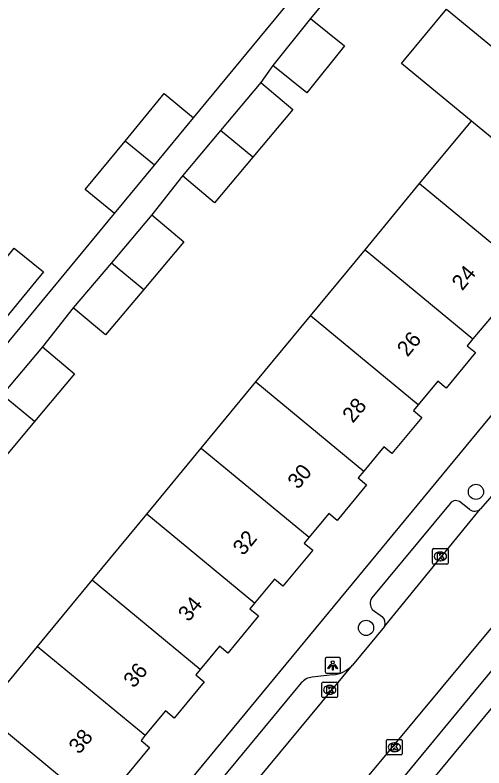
# Model space of a CAD drawing. Extents: x 162074 to 163034, y 381824 to 382557.
# Drawn here: x 162299.86 to 162330.07, y 382106.65 to 382155.17 of the extents above; entities that cross this region are included whole.
import ezdxf

# ---------------------------------------------------------------- set-up
doc = ezdxf.new("R2010")
doc.units = 0
for name, color, linetype in [('IMGEO_Boom', 7, 'Continuous'), ('IMGEO_Kolk', 7, 'Continuous'), ('IMGEO_Lichtpunt', 7, 'Continuous'), ('IMGEO_Pand', 7, 'Continuous'), ('IMGEO_Pand_nummerreeks', 7, 'Continuous'), ('IMGEO_Rijbaan_lokaal_open', 7, 'Continuous'), ('IMGEO_Voetpad_open', 7, 'Continuous')]:
    doc.layers.add(name, color=color, linetype=linetype)

msp = doc.modelspace()

# ---------------------------------------------------------------- linework, layer by layer
at = {"layer": 'IMGEO_Boom'}
for centre in [(162329.556, 382124.437), (162322.476, 382115.671)]:
    msp.add_circle(centre, 0.489, dxfattribs=at)
at = {"layer": 'IMGEO_Kolk'}
for p, q in [((162326.838, 382120.779), (162327.69, 382120.779)), ((162326.763, 382119.853), (162326.763, 382120.705)), ((162327.251, 382120.559), (162327.276, 382120.559)), ((162327.764, 382120.705), (162327.764, 382119.853)), ((162327.69, 382119.779), (162326.838, 382119.779)), ((162327.274, 382119.999), (162327.249, 382119.999)), ((162319.633, 382111.254), (162319.633, 382112.106)), ((162319.708, 382112.18), (162320.56, 382112.18)), ((162320.634, 382112.106), (162320.634, 382111.254)), ((162320.121, 382111.96), (162320.146, 382111.96)), ((162320.56, 382111.18), (162319.708, 382111.18)), ((162320.144, 382111.4), (162320.119, 382111.4)), ((162323.801, 382107.555), (162323.801, 382108.407)), ((162323.876, 382108.481), (162324.728, 382108.481)), ((162324.289, 382108.261), (162324.314, 382108.261)), ((162324.802, 382108.407), (162324.802, 382107.555)), ((162324.312, 382107.701), (162324.287, 382107.701)), ((162324.728, 382107.481), (162323.876, 382107.481))]:
    msp.add_line(p, q, dxfattribs=at)
for points in [[(162326.838, 382120.779), (162327.69, 382120.779)], [(162326.763, 382119.853), (162326.763, 382120.705)], [(162327.084, 382120.479), (162327.207, 382120.479), (162327.207, 382120.328), (162327.337, 382120.479), (162327.501, 382120.479), (162327.355, 382120.328), (162327.508, 382120.079), (162327.356, 382120.079), (162327.271, 382120.243), (162327.207, 382120.176), (162327.207, 382120.079), (162327.084, 382120.079), (162327.084, 382120.479)], [(162327.764, 382120.705), (162327.764, 382119.853)], [(162327.69, 382119.779), (162326.838, 382119.779)], [(162319.633, 382111.254), (162319.633, 382112.106)], [(162319.708, 382112.18), (162320.56, 382112.18)], [(162320.634, 382112.106), (162320.634, 382111.254)], [(162319.954, 382111.88), (162320.077, 382111.88), (162320.077, 382111.729), (162320.207, 382111.88), (162320.371, 382111.88), (162320.225, 382111.729), (162320.378, 382111.48), (162320.226, 382111.48), (162320.141, 382111.644), (162320.077, 382111.577), (162320.077, 382111.48), (162319.954, 382111.48), (162319.954, 382111.88)], [(162320.56, 382111.18), (162319.708, 382111.18)], [(162323.801, 382107.555), (162323.801, 382108.407)], [(162323.876, 382108.481), (162324.728, 382108.481)], [(162324.122, 382108.181), (162324.245, 382108.181), (162324.245, 382108.03), (162324.375, 382108.181), (162324.539, 382108.181), (162324.393, 382108.03), (162324.546, 382107.781), (162324.394, 382107.781), (162324.309, 382107.945), (162324.245, 382107.878), (162324.245, 382107.781), (162324.122, 382107.781), (162324.122, 382108.181)], [(162324.802, 382108.407), (162324.802, 382107.555)], [(162324.728, 382107.481), (162323.876, 382107.481)]]:
    msp.add_lwpolyline(points, dxfattribs=at)
for centre, start, end in [((162326.84, 382120.703), 91.552, 178.448), ((162326.84, 382120.703), 91.552, 178.448), ((162327.688, 382120.703), 1.552, 88.448), ((162327.688, 382120.703), 1.552, 88.448), ((162326.84, 382119.855), 181.552, 268.448), ((162326.84, 382119.855), 181.552, 268.448), ((162327.688, 382119.855), 271.552, 358.448), ((162327.688, 382119.855), 271.552, 358.448), ((162319.71, 382112.104), 91.552, 178.448), ((162319.71, 382112.104), 91.552, 178.448), ((162320.558, 382112.104), 1.552, 88.448), ((162320.558, 382112.104), 1.552, 88.448), ((162319.71, 382111.256), 181.552, 268.448), ((162319.71, 382111.256), 181.552, 268.448), ((162320.558, 382111.256), 271.552, 358.448), ((162320.558, 382111.256), 271.552, 358.448), ((162323.878, 382108.405), 91.552, 178.448), ((162323.878, 382108.405), 91.552, 178.448), ((162324.726, 382108.405), 1.552, 88.448), ((162324.726, 382108.405), 1.552, 88.448), ((162323.878, 382107.557), 181.552, 268.448), ((162323.878, 382107.557), 181.552, 268.448), ((162324.726, 382107.557), 271.552, 358.448), ((162324.726, 382107.557), 271.552, 358.448)]:
    msp.add_arc(centre, 0.0765, start, end, dxfattribs=at)
for centre, major_axis, ratio, start_param, end_param in [((162327.25, 382120.279), (-0.387, 0.002), 0.722429, 4.712389, 7.853982), ((162327.275, 382120.279), (-0.39, 0.002), 0.717154, 1.570796, 4.712389), ((162320.12, 382111.68), (-0.387, 0.002), 0.722429, 4.712389, 7.853982), ((162320.145, 382111.68), (-0.39, 0.002), 0.717154, 1.570796, 4.712389), ((162324.288, 382107.981), (-0.387, 0.002), 0.722429, 4.712389, 7.853982), ((162324.313, 382107.981), (-0.39, 0.002), 0.717154, 1.570796, 4.712389)]:
    msp.add_ellipse(centre, major_axis=major_axis, ratio=ratio, start_param=start_param, end_param=end_param, dxfattribs=at)
at = {"layer": 'IMGEO_Lichtpunt'}
for p, q in [((162319.832, 382113.66), (162319.832, 382112.853)), ((162319.832, 382113.66), (162319.832, 382112.853)), ((162320.734, 382113.755), (162319.926, 382113.755)), ((162320.734, 382113.755), (162319.926, 382113.755)), ((162320.828, 382112.853), (162320.828, 382113.66)), ((162320.828, 382112.853), (162320.828, 382113.66)), ((162319.926, 382112.759), (162320.734, 382112.759)), ((162319.926, 382112.759), (162320.734, 382112.759))]:
    msp.add_line(p, q, dxfattribs=at)
for points in [[(162320.206, 382113.324), (162320.245, 382113.296), (162320.057, 382113.034), (162320.019, 382113.061), (162320.206, 382113.324)], [(162320.308, 382113.276), (162320.355, 382113.276), (162320.355, 382112.954), (162320.308, 382112.954), (162320.308, 382113.276)], [(162320.418, 382113.296), (162320.456, 382113.323), (162320.643, 382113.061), (162320.604, 382113.033), (162320.418, 382113.296)]]:
    msp.add_lwpolyline(points, dxfattribs=at)
msp.add_circle((162320.331, 382113.458), 0.0994, dxfattribs=at)
for centre, start, end in [((162319.926, 382113.66), 90, 180), ((162319.926, 382113.66), 90, 180), ((162320.734, 382113.66), 0, 90), ((162320.734, 382113.66), 0, 90), ((162319.926, 382112.853), 180, 270), ((162319.926, 382112.853), 180, 270), ((162320.734, 382112.853), 270, 0), ((162320.734, 382112.853), 270, 360)]:
    msp.add_arc(centre, 0.0946, start, end, dxfattribs=at)
at = {"layer": 'IMGEO_Pand'}
for points in [[(162329.26, 382148.338), (162324.766, 382152.048), (162324.954, 382152.276), (162327.662, 382155.556), (162335.775, 382148.858), (162339.631, 382145.675), (162336.921, 382142.391), (162336.734, 382142.165)], [(162318.898, 382154.941), (162321.086, 382153.179), (162318.653, 382150.158), (162316.465, 382151.92)], [(162318.898, 382154.941), (162316.465, 382151.92)], [(162315.7, 382150.823), (162313.101, 382147.733)], [(162315.7, 382150.823), (162317.769, 382149.084), (162315.185, 382146.011)], [(162306.947, 382147.046), (162309.46, 382150.106), (162311.357, 382148.541)], [(162308.841, 382145.49), (162311.357, 382148.541)], [(162325.929, 382144.303), (162329.26, 382148.338)], [(162336.734, 382142.165), (162329.26, 382148.338)], [(162313.101, 382147.733), (162310.648, 382144.814)], [(162315.185, 382146.011), (162313.101, 382147.733)], [(162306.275, 382142.38), (162304.387, 382143.929), (162306.947, 382147.046)], [(162308.841, 382145.49), (162306.947, 382147.046)], [(162315.185, 382146.011), (162312.717, 382143.075), (162310.648, 382144.814)], [(162306.275, 382142.38), (162308.841, 382145.49)], [(162322.412, 382140.042), (162325.929, 382144.303)], [(162325.929, 382144.303), (162332.914, 382138.534)], [(162308.665, 382142.301), (162306.065, 382139.209)], [(162308.665, 382142.301), (162310.734, 382140.562), (162308.15, 382137.488)], [(162297.368, 382137.17), (162299.807, 382140.146), (162301.697, 382138.61), (162299.257, 382135.631)], [(162318.895, 382135.782), (162322.412, 382140.042)], [(162322.412, 382140.042), (162329.366, 382134.298)], [(162306.065, 382139.209), (162303.613, 382136.292)], [(162306.065, 382139.209), (162308.15, 382137.488)], [(162332.914, 382138.534), (162332.499, 382138.032), (162332.977, 382137.637), (162331.039, 382135.289), (162330.531, 382135.709), (162329.366, 382134.298)], [(162308.15, 382137.488), (162305.682, 382134.553), (162303.613, 382136.292)], [(162315.377, 382131.52), (162318.895, 382135.782)], [(162325.839, 382130.046), (162318.895, 382135.782)], [(162329.366, 382134.298), (162328.996, 382133.85), (162329.525, 382133.413), (162327.631, 382131.119), (162327.092, 382131.564), (162325.839, 382130.046)], [(162301.631, 382133.78), (162299.032, 382130.689)], [(162301.631, 382133.78), (162303.7, 382132.041), (162301.116, 382128.968)], [(162311.86, 382127.26), (162315.377, 382131.52)], [(162315.377, 382131.52), (162322.333, 382125.776)], [(162301.116, 382128.968), (162299.032, 382130.689)], [(162325.839, 382130.046), (162325.538, 382129.681), (162326.071, 382129.241), (162324.147, 382126.91), (162323.625, 382127.341), (162322.333, 382125.776)], [(162301.116, 382128.968), (162298.648, 382126.032), (162296.579, 382127.771)], [(162308.343, 382122.999), (162311.86, 382127.26)], [(162311.86, 382127.26), (162318.81, 382121.519)], [(162322.333, 382125.776), (162321.977, 382125.345), (162322.515, 382124.901), (162320.616, 382122.599), (162320.072, 382123.048), (162318.81, 382121.519)], [(162304.825, 382118.739), (162308.343, 382122.999)], [(162315.29, 382117.261), (162308.343, 382122.999)], [(162318.81, 382121.519), (162318.494, 382121.136), (162319.038, 382120.686), (162317.117, 382118.359), (162316.57, 382118.811), (162315.29, 382117.261)], [(162301.308, 382114.477), (162304.825, 382118.739)], [(162311.794, 382112.982), (162304.825, 382118.739)], [(162315.29, 382117.261), (162314.992, 382116.9), (162315.544, 382116.444), (162313.571, 382114.053), (162313.04, 382114.491), (162311.794, 382112.982)], [(162297.791, 382110.217), (162301.308, 382114.477)], [(162301.308, 382114.477), (162308.244, 382108.748)], [(162311.794, 382112.982), (162311.509, 382112.637), (162312.037, 382112.201), (162310.107, 382109.864), (162309.547, 382110.326), (162308.244, 382108.748)], [(162297.791, 382110.217), (162304.754, 382104.466)], [(162308.244, 382108.748), (162307.977, 382108.424), (162308.528, 382107.969), (162306.577, 382105.606), (162306.053, 382106.039), (162304.754, 382104.466)]]:
    msp.add_lwpolyline(points, dxfattribs=at)
at = {"layer": 'IMGEO_Rijbaan_lokaal_open'}
for points in [[(162331, 382124.675), (162329.86, 382123.349)], [(162323.66, 382115.771), (162329.86, 382123.349)], [(162336.118, 382122.382), (162316.921, 382099.281)], [(162323.66, 382115.771), (162321.603, 382113.278)], [(162310.148, 382099.454), (162321.603, 382113.278)]]:
    msp.add_lwpolyline(points, dxfattribs=at)
at = {"layer": 'IMGEO_Voetpad_open'}
for points in [[(162311.357, 382148.541), (162323.43, 382163.172), (162320.732, 382165.399)], [(162344.282, 382145.986), (162324.785, 382162.075), (162318.898, 382154.941)], [(162316.465, 382151.92), (162315.7, 382150.823)], [(162292.703, 382083.506), (162344.282, 382145.986)], [(162310.648, 382144.814), (162308.665, 382142.301)], [(162280.011, 382110.569), (162306.275, 382142.38)], [(162303.613, 382136.292), (162301.631, 382133.78)], [(162352.042, 382136.478), (162351.891, 382136.294), (162317.774, 382095.055)], [(162327.89, 382123.697), (162322.838, 382117.599)], [(162329.14, 382123.312), (162328.579, 382123.752)], [(162320.226, 382100.372), (162336.497, 382120.103)], [(162322.874, 382116.853), (162323.539, 382116.389)], [(162320.318, 382112.646), (162319.012, 382112.498)], [(162318.303, 382112.123), (162309.358, 382101.318)]]:
    msp.add_lwpolyline(points, dxfattribs=at)
for centre, radius, start, end in [((162328.26, 382123.399), 0.475, 47.934, 141.194), ((162329.478, 382123.762), 0.562, 233.0864, 312.7972), ((162323.433, 382117.254), 0.688, 149.9047, 215.6209), ((162323.141, 382115.99), 0.563, 337.1001, 45.0558), ((162320.192, 382114.524), 1.882, 273.8242, 318.5544), ((162319.124, 382111.429), 1.075, 95.9673, 139.7826)]:
    msp.add_arc(centre, radius, start, end, dxfattribs=at)

# ---------------------------------------------------------------- texts
at = {"layer": 'IMGEO_Pand_nummerreeks'}
for s, p in [('24', (162328.674, 382137.359)), ('26', (162325.148, 382133.09)), ('28', (162321.625, 382128.822)), ('30', (162318.099, 382124.553)), ('32', (162314.569, 382120.279)), ('34', (162311.045, 382116.013)), ('36', (162307.519, 382111.743)), ('38', (162303.995, 382107.476))]:
    msp.add_text(s, height=1, rotation=50.4475, dxfattribs=at).set_placement(p)

doc.saveas('drawing.dxf')
